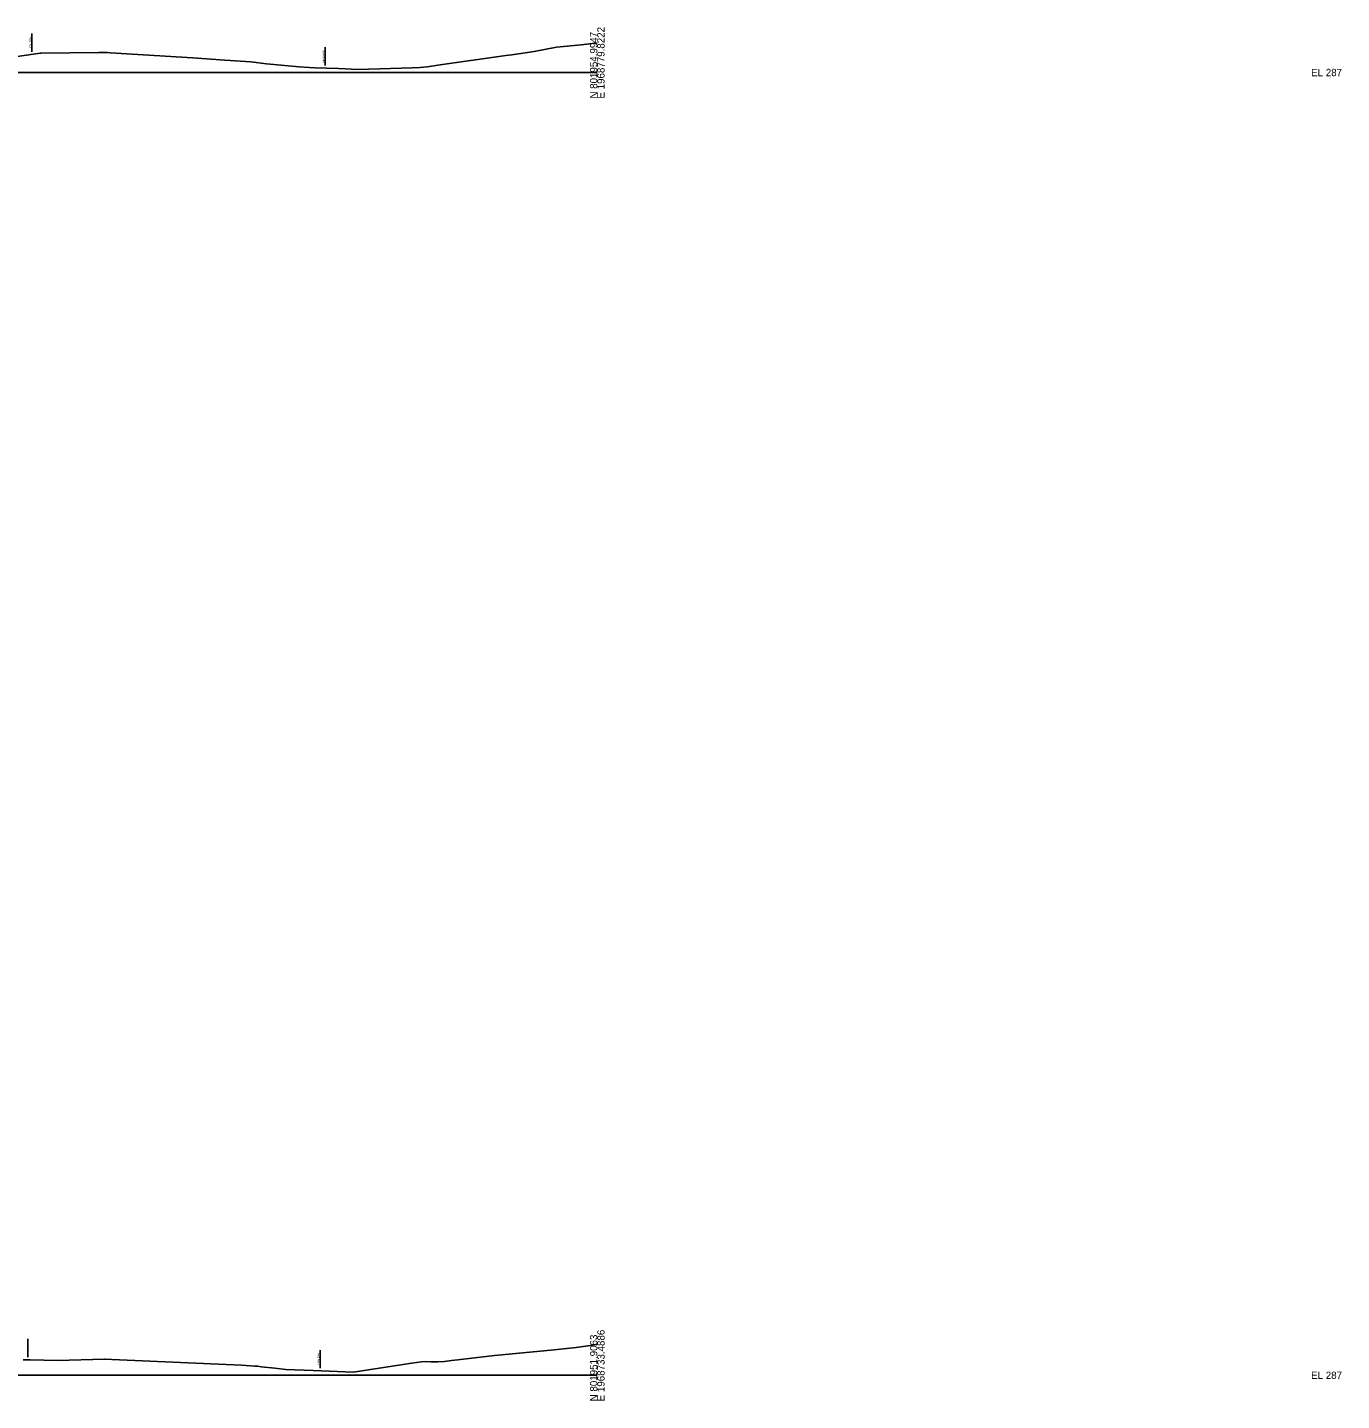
# Model space of a CAD drawing. Extents: x -4026 to 9638, y -10 to 19609.
# Drawn here: x 5481 to 5986, y 4990 to 5517 of the extents above; entities that cross this region are included whole.
import ezdxf

# ---------------------------------------------------------------- set-up
doc = ezdxf.new("R2010")
doc.units = 0
for name, color, linetype in [('RD_GPK_XS_Cell', 7, 'Continuous'), ('RD_XS_ExGround', 7, 'Continuous'), ('RD_XS_ExRW', 7, 'Continuous'), ('RD_XS_NewRW', 7, 'Continuous')]:
    doc.layers.add(name, color=color, linetype=linetype)

msp = doc.modelspace()

# ---------------------------------------------------------------- linework, layer by layer
at = {"layer": 'RD_GPK_XS_Cell'}
for p, q in [((5350, 5500), (5700, 5500)), ((5350, 5000), (5700, 5000))]:
    msp.add_line(p, q, dxfattribs=at)
at = {"layer": 'RD_XS_ExGround'}
for points in [[(5469.32, 5504.94), (5486.13, 5507.42), (5486.58, 5507.43), (5508.49, 5507.66), (5512.05, 5507.66), (5513.06, 5507.6), (5544.7, 5505.64), (5557.07, 5504.75), (5567.08, 5504.05), (5573.03, 5503.38), (5585.56, 5502.23), (5589.58, 5501.92), (5591.74, 5501.82), (5600.69, 5501.5), (5608.26, 5501.22), (5629.01, 5501.83), (5631.97, 5501.98), (5634.87, 5502.2), (5638.81, 5502.85), (5664.93, 5506.56), (5667.23, 5506.8), (5675.77, 5508.12), (5684.36, 5509.68), (5693.8, 5510.63), (5694.79, 5510.74), (5695.95, 5510.9), (5700, 5511.43)], [(5479.6, 5005.95), (5482.37, 5005.97), (5492.86, 5005.68), (5510.8, 5006.2), (5511.11, 5006.2), (5513.68, 5006.11), (5563.38, 5003.86), (5568.55, 5003.55), (5569.59, 5003.51), (5570.99, 5003.2), (5576.23, 5002.77), (5580.5, 5002.26), (5590.96, 5001.79), (5606.28, 5001.18), (5625.46, 5004.17), (5628.67, 5004.65), (5632.5, 5005.22), (5634.06, 5005.35), (5636.12, 5005.18), (5638.86, 5005.12), (5641.38, 5005.32), (5644.05, 5005.68), (5646.52, 5005.95), (5660.6, 5007.59), (5663.34, 5007.84), (5683.39, 5009.72), (5691.89, 5010.65), (5700, 5011.78)]]:
    msp.add_lwpolyline(points, dxfattribs=at)
at = {"layer": 'RD_XS_ExRW'}
for p, q in [((5483.02, 5507.96), (5483.02, 5514.96)), ((5481.4, 5006.96), (5481.4, 5013.96))]:
    msp.add_line(p, q, dxfattribs=at)
at = {"layer": 'RD_XS_NewRW'}
for p, q in [((5595.55, 5502.68), (5595.55, 5509.68)), ((5593.67, 5002.68), (5593.67, 5009.68))]:
    msp.add_line(p, q, dxfattribs=at)

# ---------------------------------------------------------------- texts
at = {"layer": 'RD_GPK_XS_Cell'}
for s, p in [('N 801954.9947', (5700, 5490)), ('E 1968779.8222', (5702.8, 5490)), ('E 1968733.4886', (5702.8, 4990)), ('N 801951.9063', (5700, 4990))]:
    msp.add_text(s, height=2.8, rotation=90, dxfattribs=at).set_placement(p)
for p in [(5974, 5498.6), (5974, 4998.6)]:
    msp.add_text('EL 287', height=2.8, dxfattribs=at).set_placement(p)
at = {"layer": 'RD_XS_ExRW'}
msp.add_text('EX. R/W ', height=0.75, rotation=90, dxfattribs=at).set_placement((5482.77, 5509.64))
at = {"layer": 'RD_XS_NewRW'}
for p in [(5595.3, 5503.83), (5593.42, 5003.83)]:
    msp.add_text('NEW R/W ', height=0.75, rotation=90, dxfattribs=at).set_placement(p)

doc.saveas('drawing.dxf')
